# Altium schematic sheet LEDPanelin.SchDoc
size A4; SheetNumber: 2; SheetTotal: 2
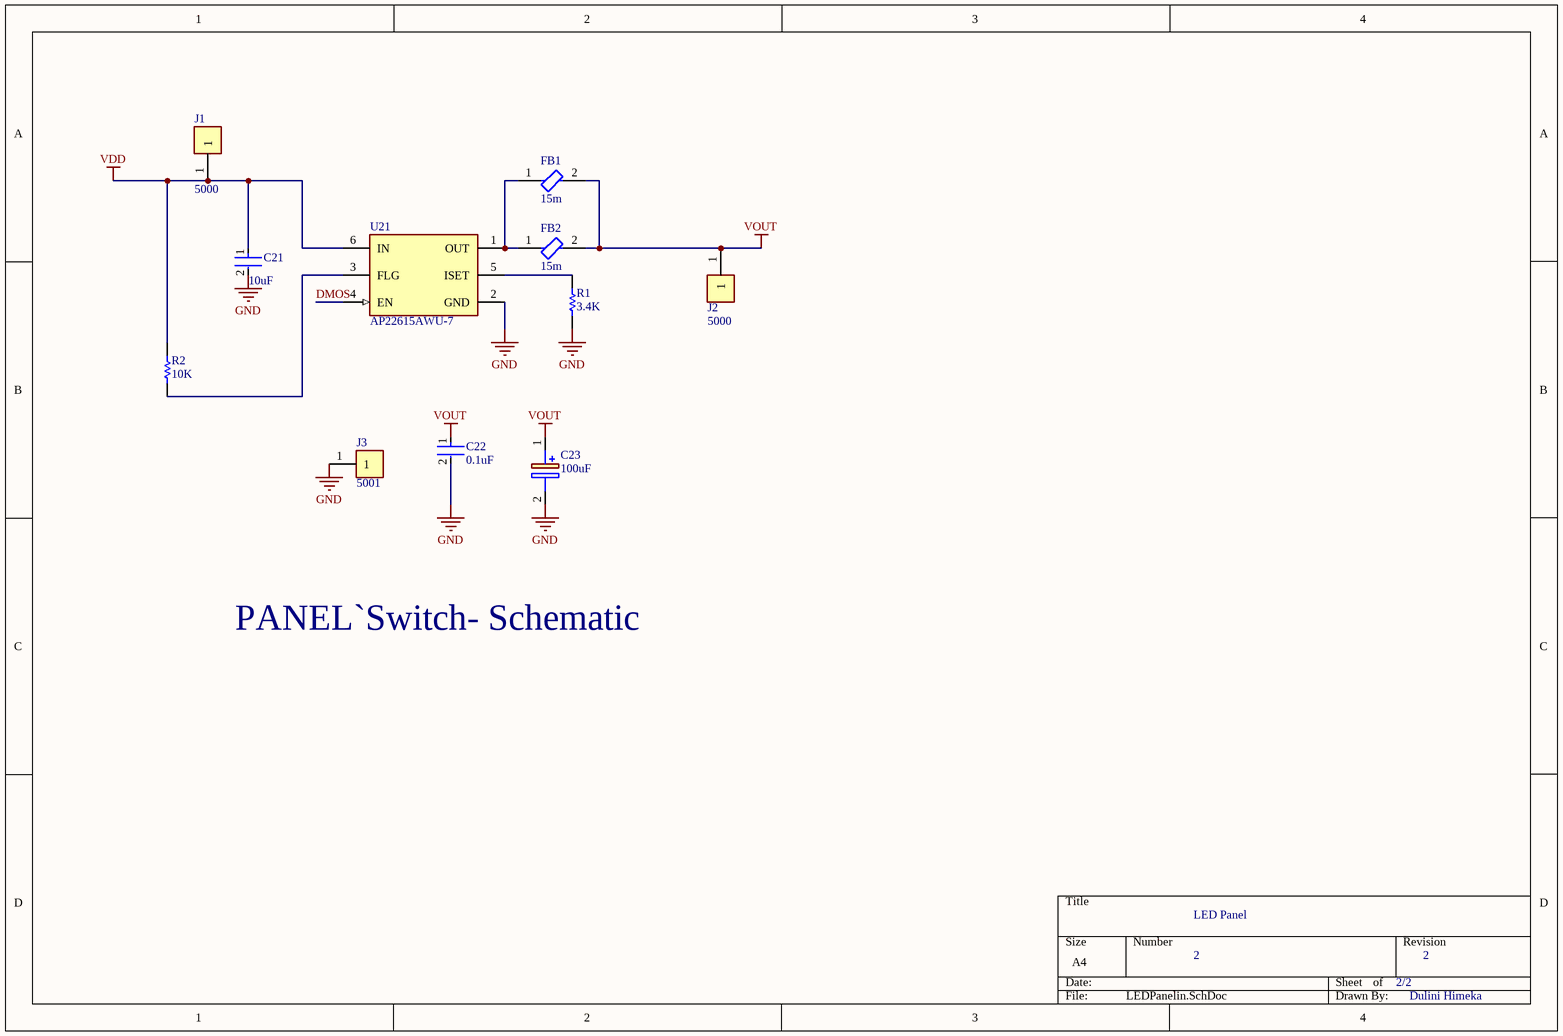
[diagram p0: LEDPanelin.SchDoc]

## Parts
C21  10uF  [FP-1206-L_3_2_0_2-W_1_6_0-IPC_A]
C22  0.1uF  [FP-C1206C-EB-MFG]
C23  100uF  [CAPAE660X565N]
FB1  15m  [FP-BLM21-0_2-t0_85-e0_5-d-IPC_B]
FB2  15m  [FP-BLM21-0_2-t0_85-e0_5-d-IPC_B]
J1  5000  [FP-5000-MFG]
J2  5000  [FP-5000-MFG]
J3  5001  [FP-5001-MFG]
R1  3.4K  [RESC3216X70X50LL05T20]
R2  10K  [RESC3116X65X40ML10T20]
U21  AP22615AWU-7  [FP-TSOT26-IPC_B]

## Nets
GND: C21.2 C22.2 C23.2(-) J3.1 R1.1 U21.2(GND)
VDD: C21.1 J1.1 R2.2 U21.6(IN)
VOUT: C22.1 C23.1(+) FB1.2 FB2.2 J2.1
DMOS: U21.4(EN)
NetFB1_1: FB1.1 FB2.1 U21.1(OUT)
NetR1_2: R1.2 U21.5(ISET)
NetR2_1: R2.1 U21.3(FLG)

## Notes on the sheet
- PANEL`Switch- Schematic
- LED Panel
- 2
- 2/2
- Dulini Himeka

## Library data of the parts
C21 = CMP-04427-021870-1: General Purpose Ceramic Capacitor, 1206, 10uF, 10%, X5R, 15%, 10V
C22 = CMP-03020-000153-1: CAP CER 0.1UF 100V X7R 1206; Manufacturer: KEMET; Manufacturer Part Number: C1206C104K1RACTU; Value: 0.10 μF; Tolerance: 0.1; Material: Ceramic; Temperature Coefficient: 15%; Automotive Grade: Grade 0
C23 = EEV107M016S9GAA: Capacitor Polarised; Manufacturer_Name: KEMET
FB1 FB2 = CMP-06046-001820-1: Chip Ferrite Bead, 0805, 30Ω @ 100MHz, 0.014Ω, , 4A; Impedance: 30R; Shielding: Unshielded; Max DC Current: 3A; Tolerance: 25%; DC Resistance (DCR): 14mR; Material: Steel; Number of Lines: 1; DC Resistance-Max: 15MR
J1 J2 = CMP-19636-000027-1: PC TEST POINT MINIATURE RED; Outside Diameter: 2.54mm; Body Material: Bronze; Number of Contacts: 1; Insulation: Insulated; Inside Diameter: 1.27mm; Hole Diameter: 1.6mm; Plating: Silver
J3 = CMP-2000-05181-2: PC TEST POINT MINIATURE BLACK; Body Material: Bronze; Plating: Silver; Inside Diameter: 1.27mm; Hole Diameter: 1.6mm; Number of Ports: 1; Outside Diameter: 2.54mm; Insulation: Insulated
R1 = CMP-2003-00314-1: Part Number: ERJ-8ENF3401V; Manufacturer: Panasonic
R2 = CMP-1014-00623-2: Chip Resistor, 10 KOhm, +/- 1%, 0.25 W, -55 to 155 degC, 1206 (3216 Metric), RoHS, Tape and Reel; Manufacturer: Yageo; Voltage Rating: 200V; Resistance: 10KOhm; Temperature Coefficient: 100ppm/degreesC; Power Rating: 250mW
U21 = CMP-12757-000023-1: IC PWR SWTCH N/P-CHAN 1:1 TSOT26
